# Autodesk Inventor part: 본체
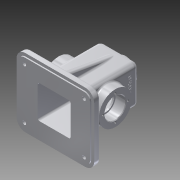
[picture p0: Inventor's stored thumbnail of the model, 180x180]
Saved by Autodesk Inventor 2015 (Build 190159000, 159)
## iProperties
Created: 2016-02
Part Number: 본체
Material: 알루미늄 6061
Document SubType Name: Modeling
Designer: Administrator
Density: 2.7 g/cm^3
Appearance: 알루미늄 - 평지
Mass: 852.312 g
Surface Area: 910.133 cm^2
Volume: 315.671 cm^3
Author: Administrator
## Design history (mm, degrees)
sketch "스케치1"
  geometry: L1 (60, 52.5)-(-60, 52.5); L2 (-60, 52.5)-(-60, -52.5); L3 (-60, -52.5)-(60, -52.5); L4 (60, -52.5)-(60, 52.5); L5 (60, 52.5)-(-60, -52.5); L6 (-60, 52.5)-(60, -52.5); 1 further point
  constraints: 12 end point, 2 midpoint, 2 parallel, 1 horizontal, 1 perpendicular
  dimensions: "d0" = 120 distance of L3.end L2.end; "d1" = 105 distance of L2.end L1.end
extrude "돌출1" new body sketch "스케치1" distance "d2" = 2; taper "d3" = 0 deg
sketch "스케치2"
  geometry: L1 (65, -57.5)-(-65, -57.5); L2 (-65, -57.5)-(-65, 57.5); L3 (-65, 57.5)-(65, 57.5); L4 (65, 57.5)-(65, -57.5); L5 (65, -57.5)-(-65, 57.5); L6 (-65, -57.5)-(65, 57.5); 1 further point
  constraints: 12 end point, 2 midpoint, 2 parallel, 1 horizontal, 1 perpendicular
  dimensions: "d4" = 130 distance of L2.end L3.end; "d5" = 115 distance of L1.end L2.end
extrude "돌출2" join sketch "스케치2" distance "d6" = 10; taper "d7" = 0 deg
sketch "스케치3"
  geometry: L1 (60, 52.5)-(60, -52.5) reference; L2 (60, -52.5)-(-60, -52.5) reference; L3 (-60, -52.5)-(-60, 52.5) reference; L4 (-60, 52.5)-(60, 52.5) reference; L5 (32.5, 32.5)-(-32.5, 32.5); L6 (-32.5, 32.5)-(-32.5, -32.5); L7 (-32.5, -32.5)-(32.5, -32.5); L8 (32.5, -32.5)-(32.5, 32.5); L9 (32.5, 32.5)-(-32.5, -32.5); L10 (-32.5, 32.5)-(32.5, -32.5); 1 further point
  constraints: 12 end point, 2 midpoint, 2 parallel, 1 horizontal, 1 perpendicular
  dimensions: "d8" = 65 distance of L7.end L6.end; "d9" = 65 distance of L6.end L5.end
extrude "돌출3" join sketch "스케치3" distance "d10" = 110; taper "d11" = 0 deg
sketch "스케치4"
  geometry: L1 (2, 52.5)-(2, 57.5) reference; L2 (2, 57.5)-(12, 57.5) reference; L3 (12, 57.5)-(12, 32.5) reference; L4 (12, 32.5)-(110, 32.5) reference; L5 (110, 32.5)-(110, -32.5) reference; L6 (110, -32.5)-(12, -32.5) reference; L7 (12, -32.5)-(12, -57.5) reference; L8 (12, -57.5)-(2, -57.5) reference; L9 (2, -57.5)-(2, -52.5) reference; L10 (2, -52.5)-(0, -52.5) reference; L11 (0, -52.5)-(0, 52.5) reference; L12 (0, 52.5)-(2, 52.5) reference; L13 (55, -32.5)-(55, 32.5); C1 r 27.5 at (55, 0); 2 further points
  constraints: 2 end point, 2 midpoint, 2 point on line, 1 centre point, 1 horizontal alignment, 1 vertical
  dimensions: "d12" = 55 distance between parallel lines of L11 L13; "d13" = 55 diameter of C1
extrude "돌출4" join sketch "스케치4" stored distance "d14" = 95; taper "d15" = 0 deg
sketch "스케치5"
  geometry: C1 r 20 at (0, 0); 1 further point
  constraints: 1 centre point, 1 coincident
  dimensions: "d16" = 40 diameter of C1
extrude "돌출5" join sketch "스케치5" distance "d17" = 10; taper "d18" = 0 deg
sketch "스케치7"
  geometry: L1 (2, 52.5)-(2, 57.5) reference; L2 (2, 57.5)-(12, 57.5) reference; L3 (12, 57.5)-(12, 32.5) reference; L4 (12, 32.5)-(110, 32.5) reference; L5 (110, 32.5)-(110, 20) reference; L6 (110, 20)-(120, 20) reference; L7 (120, 20)-(120, -20) reference; L8 (120, -20)-(110, -20) reference; L9 (110, -20)-(110, -32.5) reference; L10 (110, -32.5)-(12, -32.5) reference; L11 (12, -32.5)-(12, -57.5) reference; L12 (12, -57.5)-(2, -57.5) reference; L13 (2, -57.5)-(2, -52.5) reference; L14 (2, -52.5)-(0, -52.5) reference; L15 (0, -52.5)-(0, 52.5) reference; L16 (0, 52.5)-(2, 52.5) reference; L17 (97.069, 32.5)-(12, 47.5); L18 (12, -57.5)-(12, 57.5) reference; L19 (97.069, 32.5)-(97.069, -32.5); L20 (12, -32.5)-(110, -32.5) reference; L21 (97.069, -32.5)-(12, -47.5); L22 (12, 47.5)-(12, -47.5); 1 further point
  constraints: 8 end point, 4 point on line, 1 collinear, 1 perpendicular
  dimensions: "d22" = 10 deg angle of L17 L2; "d23" = 10 deg angle of L12 L21; "d24" = 10 distance of L11.end L21.end
extrude "돌출6" join sketch "스케치7" stored distance "d25" = 10; taper "d26" = 0 deg
hole "구멍1" diameter "d32" = 35; stored, may be unused: countersink angle "d36" = 90 deg, drill point angle "d38" = 0 deg; dims "d33" = 6, "d34" = 4, "d35" = 2, "d37" = 17, "d144" = 10, "d145" = 10
hole "구멍2" diameter "d41" = 21; stored, may be unused: countersink angle "d45" = 90 deg, drill point angle "d47" = 118 deg; dims "d39" = 10, "d40" = 10, "d42" = 6, "d43" = 4, "d44" = 2, "d46" = 8
fillet "모깎기1" dims "d48" = 15
fillet "모깎기2" dims "d49" = 8
feature "면 기울기1" dims angle "d50" = 5 deg
fillet "모깎기3" dims "d51" = 8
sketch "스케치9"
  geometry: L1 (-49, 0)-(0, 0) reference; L2 (-27.5, 0)-(-21.5, 0); L3 (-21.5, 0)-(-21.5, 18); L4 (-21.5, 18)-(-27.5, 18); L5 (-27.5, 18)-(-27.5, 0); A1 r 27.5 centre (-24.5, 43) between (-49, 30.51) and (0, 30.51) reference; 1 further point
  constraints: 8 end point, 2 parallel, 1 horizontal, 1 perpendicular, 1 point on line
  dimensions: "d52" = 6 distance of L4.end L3.end; "d53" = 3 distance from line of L3 A1.centre; "d54" = 18 distance of L2.end L3.end
extrude "돌출7" join sketch "스케치9" distance "d55" = 10; taper "d56" = 0 deg
sketch "스케치10"
  geometry: L1 (-5, -32.5)-(-24.5, -32.5) reference; L2 (-32.5, -24.5)-(-32.5, -3) reference; L3 (-32.5, -3)-(-42.5, -3) reference; L4 (-42.5, -3)-(-42.5, 3) reference; L5 (-42.5, 3)-(-32.5, 3) reference; L6 (-32.5, 3)-(-32.5, 24.5) reference; L7 (-24.5, 32.5)-(-5, 32.5) reference; L8 (-5, 32.5)-(-5, 47.5) reference; L9 (-5, 47.5)-(5, 47.5) reference; L10 (5, 47.5)-(5, 32.5) reference; L11 (5, 32.5)-(24.5, 32.5) reference; L12 (32.5, 24.5)-(32.5, 3) reference; L13 (32.5, 3)-(42.5, 3) reference; L14 (42.5, 3)-(42.5, -3) reference; L15 (42.5, -3)-(32.5, -3) reference; L16 (32.5, -3)-(32.5, -24.5) reference; L17 (24.5, -32.5)-(5, -32.5) reference; L18 (5, -32.5)-(5, -47.5) reference; L19 (5, -47.5)-(-5, -47.5) reference; L20 (-5, -47.5)-(-5, -32.5) reference; L21 (65, 42.5)-(65, -42.5) reference; L22 (50, -57.5)-(-50, -57.5) reference; L23 (-65, -42.5)-(-65, 42.5) reference; L24 (-50, 57.5)-(50, 57.5) reference; C1 r 7.5 at (50, 42.5); C2 r 7.5 at (50, -42.5); C3 r 7.5 at (-50, -42.5); C4 r 7.5 at (-50, 42.5); C5 r 10.5 at (0, 0) reference; A1 r 8 centre (-24.5, -24.5) between (-32.5, -24.5) and (-24.5, -32.5) reference; A2 r 8 centre (-24.5, 24.5) between (-24.5, 32.5) and (-32.5, 24.5) reference; A3 r 8 centre (24.5, 24.5) between (32.5, 24.5) and (24.5, 32.5) reference; A4 r 8 centre (24.5, -24.5) between (24.5, -32.5) and (32.5, -24.5) reference; A5 r 15 centre (50, 42.5) between (65, 42.5) and (50, 57.5) reference; A6 r 15 centre (50, -42.5) between (50, -57.5) and (65, -42.5) reference; A7 r 15 centre (-50, -42.5) between (-65, -42.5) and (-50, -57.5) reference; A8 r 15 centre (-50, 42.5) between (-50, 57.5) and (-65, 42.5) reference; 1 further point
  constraints: 4 centre point, 4 coincident, 3 equal radius
  dimensions: "d57" = 15 diameter of C1
extrude "돌출8" join sketch "스케치10" distance "d58" = 1; taper "d59" = 0 deg
hole "구멍3" diameter "d62" = 6; stored, may be unused: countersink angle "d66" = 90 deg, drill point angle "d68" = 118 deg; dims "d60" = 10, "d61" = 10, "d63" = 6, "d64" = 4, "d65" = 2, "d67" = 8
hole "구멍4" diameter "d71" = 6; stored, may be unused: countersink angle "d75" = 90 deg, drill point angle "d77" = 118 deg; dims "d69" = 10, "d70" = 10, "d72" = 6, "d73" = 4, "d74" = 2, "d76" = 8
hole "구멍5" diameter "d80" = 6; stored, may be unused: countersink angle "d84" = 90 deg, drill point angle "d86" = 118 deg; dims "d78" = 10, "d79" = 10, "d81" = 6, "d82" = 4, "d83" = 2, "d85" = 8
hole "구멍6" diameter "d89" = 6; stored, may be unused: countersink angle "d93" = 90 deg, drill point angle "d95" = 118 deg; dims "d87" = 10, "d88" = 10, "d90" = 6, "d91" = 4, "d92" = 2, "d94" = 8
sketch "스케치11" dims "d96" = 29
  geometry: C1 r 10.5 at (0, 0) reference; C2 r 19.125 at (0, 0) reference; 2 further points
  constraints: 2 vertical alignment, 1 coincident, 2 other
hole "구멍7" sketch "스케치11" at (0, 14.5) diameter "d97" = 2.459; stored, may be unused: countersink angle "d101" = 90 deg, drill point angle "d103" = 118 deg; dims "d98" = 7, "d99" = 4, "d100" = 2, "d102" = 9
sketch "스케치12" dims "d104" = 42
  geometry: C1 r 17.5 at (0, 0) reference; C2 r 27.5 at (0, 0) reference; 3 further points
  constraints: 2 vertical alignment, 1 coincident, 2 other
hole "구멍8" sketch "스케치12" at (0, 21) diameter "d105" = 3.242; stored, may be unused: countersink angle "d109" = 90 deg, drill point angle "d111" = 118 deg; dims "d106" = 8, "d107" = 4, "d108" = 2, "d110" = 10
node "작업 평면1"
sketch "스케치13"
  geometry: L1 (-32.5, 47)-(-32.5, -43) reference; L2 (24.5, 55)-(-24.5, 55) reference; L3 (32.5, -43)-(32.5, 47) reference; L4 (19.125, 65)-(-19.125, 65) reference; 2 further points
  constraints: 1 other
  dimensions: "d119" = 32.5 distance from line of L1 point (0, 39); "d179" = 26 distance from line of L4 point (0, 39)
feature "엠보싱1" sketch "스케치13" dims "d121" = 0.5, "d122" = 0
chamfer "모따기1" distance "d123" = 1; stored, may be unused: second distance "d124" = 2, angle "d125" = 45 deg
chamfer "모따기2" distance "d126" = 1; stored, may be unused: second distance "d127" = 2, angle "d128" = 45 deg
fillet "모깎기4" dims "d132" = 3
fillet "모깎기5" dims "d133" = 3
fillet "모깎기6" dims "d134" = 3
fillet "모깎기7" dims "d135" = 3
fillet "모깎기8" dims "d136" = 3
fillet "모깎기9" dims "d137" = 3
fillet "모깎기10" dims "d138" = 3
fillet "모깎기11" dims "d139" = 3
fillet "모깎기12" dims "d140" = 3
fillet "모깎기13" dims "d141" = 3
fillet "모깎기15" dims "d143" = 1
hole "구멍9" diameter "d148" = 35; stored, may be unused: countersink angle "d152" = 90 deg, drill point angle "d154" = 0 deg; dims "d146" = 10, "d147" = 10, "d149" = 8, "d150" = 4, "d151" = 2, "d153" = 17
hole "구멍10" diameter "d157" = 30; stored, may be unused: countersink angle "d161" = 90 deg, drill point angle "d163" = 0 deg; dims "d155" = 10, "d156" = 10, "d158" = 8, "d159" = 4, "d160" = 2, "d162" = 17
fillet "모깎기16" dims "d164" = 0.3
chamfer "모따기4" distance "d165" = 1; stored, may be unused: second distance "d166" = 2, angle "d167" = 45 deg
fillet "모깎기17" dims "d168" = 10
sketch "스케치14"
  geometry: L1 (27.5, -27.5)-(-27.5, -27.5); L2 (-27.5, -27.5)-(-27.5, 27.5); L3 (-27.5, 27.5)-(27.5, 27.5); L4 (27.5, 27.5)-(27.5, -27.5); L5 (27.5, -27.5)-(-27.5, 27.5); L6 (-27.5, -27.5)-(27.5, 27.5); C1 r 10.5 at (0, 0) reference
  constraints: 12 end point, 2 parallel, 1 horizontal, 1 perpendicular
  dimensions: "d169" = 55 distance of L2.end L3.end; "d170" = 55 distance of L1.end L2.end; "d173" = 27.5 distance from line of L3 C1.centre; "d174" = 27.5 distance from line of L2 C1.centre
extrude "돌출10" cut sketch "스케치14" distance "d175" = 105; taper "d176" = 0 deg
fillet "모깎기18" dims "d177" = 3
fillet "모깎기19" dims "d178" = 3
fillet "모깎기20" dims "d180" = 3
node "솔리드1"
mirror "대칭1"
pattern_circular "원형 패턴1" dims angle "d113" = 360 deg
pattern_circular "원형 패턴2" dims angle "d116" = 360 deg
mirror "대칭2"
node "절단 모서리 투영1"
node "절단 모서리 투영2"
node "절단 모서리 투영4"
node "절단 모서리 투영6"
other parameters: "d118" = 22.5
